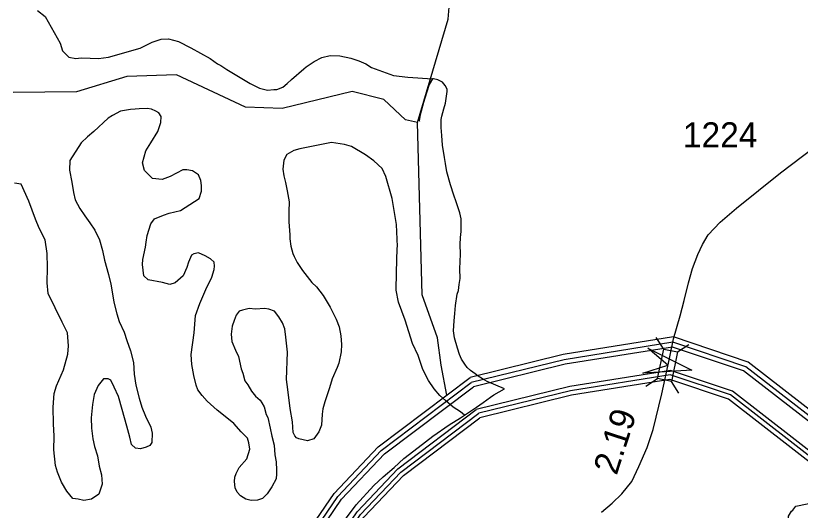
# Model space of a CAD drawing. Extents: x 2206922 to 2357709, y 510027 to 673830.
# Drawn here: x 2254245 to 2258161, y 585306 to 587773 of the extents above; entities that cross this region are included whole.
import ezdxf

# ---------------------------------------------------------------- set-up
doc = ezdxf.new("R2010")
doc.units = 0
for name, color, linetype in [('Exist Hydrographic Buffer Line', 7, 'Continuous'), ('Exist Hydrographic Creek Single Shore', 7, 'Continuous'), ('Exist Hydrographic Misc Water Feature', 7, 'Continuous'), ('Exist Hydrographic River Shore', 7, 'Continuous'), ('Exist Road Secondary Mileage Hundredths English Label', 7, 'Continuous'), ('Exist Road Secondary Structure Standard Bridge Attributed CELL', 7, 'Continuous'), ('Exist Road Secondary Structure Standard Bridge CELL', 7, 'Continuous'), ('Exist Road Secondary Type 51 Attributed', 7, 'Continuous'), ('Exist Road Secondary Type 51 Number Label', 7, 'Continuous')]:
    doc.layers.add(name, color=color, linetype=linetype)

msp = doc.modelspace()

# ---------------------------------------------------------------- linework, layer by layer
at = {"layer": 'Exist Hydrographic Buffer Line'}
for points in [[(2258439.8, 585595.2), (2257889, 586022.3), (2257525.7, 586143.9), (2256983.5, 586057.1), (2256519.2, 585943.3)], [(2258438.4, 585566.9), (2257877.9, 586001.6), (2257523.8, 586120.1), (2256988.1, 586034.4), (2256529.4, 585921.9)], [(2258495.1, 585470.3), (2258292.3, 585536.2), (2257823.5, 585899.8), (2257514.2, 586003.3), (2257010.6, 585922.7), (2256543.9, 585808.3)], [(2258496, 585447.9), (2258282.3, 585517.4), (2257813.4, 585881.1), (2257512.4, 585981.8), (2257014.8, 585902.2), (2256556.8, 585789.9)], [(2252449.5, 583777.6), (2252896.9, 583265.7), (2253032.5, 583222.4), (2253650, 583251.5), (2254012.5, 583205.2), (2254333.4, 583238.1), (2254389.7, 583270.4), (2254409.6, 583296.3), (2254490.2, 583536.5), (2254623, 583729.3), (2254736.7, 583794.1), (2255167, 584224.3), (2255561.4, 584946.9), (2255853.6, 585375.5), (2256070.1, 585604.4), (2256519.2, 585943.3)], [(2252443.6, 583749.1), (2252883.7, 583245.6), (2253029.4, 583199), (2253649.1, 583228.2), (2254012.2, 583181.9), (2254340.6, 583215.5), (2254405.3, 583252.6), (2254430.3, 583285.2), (2254511.1, 583526), (2254639.1, 583711.8), (2254750.9, 583775.5), (2255185.7, 584210.3), (2255581.2, 584934.8), (2255871.7, 585360.9), (2256085.6, 585587.1), (2256529.4, 585921.9)], [(2252451, 583555.4), (2252814.3, 583139.8), (2253013.2, 583076.2), (2253644.2, 583105.9), (2254010.7, 583059.2), (2254378.8, 583096.9), (2254487.1, 583159.1), (2254539.4, 583227.1), (2254621.3, 583471), (2254723.7, 583619.7), (2254825.5, 583677.7), (2255284.4, 584136.5), (2255685.3, 584871.1), (2255966.9, 585284.2), (2256167.2, 585495.9), (2256556.8, 585789.9)], [(2252461, 583578.1), (2252827.1, 583159.3), (2253016.2, 583098.9), (2253645.1, 583128.5), (2254011, 583081.9), (2254371.8, 583118.7), (2254472, 583176.3), (2254519.3, 583237.9), (2254601, 583481.1), (2254708.1, 583636.7), (2254811.7, 583695.7), (2255266.2, 584150.1), (2255666.1, 584882.8), (2255949.4, 585298.4), (2256152.1, 585512.7), (2256543.9, 585808.3)]]:
    msp.add_lwpolyline(points, dxfattribs=at)
at = {"layer": 'Exist Hydrographic Creek Single Shore'}
for points in [[(2256250.4, 587239.9), (2256404.4, 587754.9), (2256411.4, 587856.5)], [(2256250.4, 587239.9), (2256191.4, 587254.2), (2256082.5, 587354.8), (2255924.4, 587394), (2255575.4, 587309.3), (2255391.4, 587316.3), (2255048.4, 587477.4), (2254799.3, 587469.3), (2254549.3, 587392.4), (2254233.3, 587388.9)], [(2256397, 585880.8), (2256368.3, 586030.5), (2256350.5, 586165.4), (2256274.4, 586380.1), (2256250.4, 587239.9)], [(2258100.4, 585249.8), (2258101.8, 585264.2), (2258101.6, 585276), (2258117.4, 585302), (2258123.8, 585306.3), (2258139.3, 585326.2), (2258195.5, 585338.9), (2258359, 585366.1), (2258369.2, 585368.3), (2258375, 585370.2), (2258383, 585374.3), (2258391.2, 585380.4), (2258396.7, 585388.4)]]:
    msp.add_lwpolyline(points, dxfattribs=at)
at = {"layer": 'Exist Hydrographic Misc Water Feature'}
msp.add_line((2256631.6, 585881.6), (2256685.1, 585912.1), dxfattribs=at)
for points in [[(2254353.5, 587798.6), (2254391.8, 587768.8), (2254466.5, 587635.5), (2254479, 587597.6), (2254495.4, 587581.7), (2254511, 587565.9), (2254545.4, 587560), (2254571.2, 587562.1), (2254617.2, 587560.5), (2254659, 587559.1), (2254709, 587565.3), (2254866.5, 587610.5), (2254892.3, 587624.8), (2254926.4, 587641.2)], [(2254926.4, 587641.2), (2254972.1, 587655.4), (2255008.2, 587657.6), (2255057.8, 587644.1), (2255120.2, 587612.8), (2255215.1, 587559.6), (2255253, 587531.9), (2255269, 587523.8), (2255299.4, 587504.3), (2255357.6, 587468.7), (2255415.8, 587435.2), (2255461.6, 587411.7), (2255501.8, 587402), (2255534, 587404), (2255547.9, 587404.3), (2255578, 587416.4), (2255599.8, 587434.6), (2255621.5, 587454.9), (2255682.8, 587507.3), (2255694.7, 587517.3), (2255734.9, 587543.7), (2255772.6, 587563.9), (2255814.3, 587574.2), (2255862.5, 587572.6), (2255918.4, 587561.4), (2255958.6, 587547.6), (2255992.5, 587532), (2256021, 587513.9), (2256131.1, 587475), (2256202.8, 587465.4), (2256325, 587458.3)], [(2256325, 587458.3), (2256309.3, 587430.3), (2256297.4, 587392.3), (2256280.3, 587340.2), (2256264.4, 587278.1), (2256258.2, 587250.7), (2256260.9, 587246.2)], [(2256685.1, 585912.1), (2256599.2, 585947.8), (2256575.2, 585961.1), (2256552.9, 585975), (2256539.1, 585986.8), (2256514.9, 586002.7), (2256498.9, 586018.5), (2256486.6, 586034.5), (2256470.6, 586060.4), (2256460.2, 586082.3), (2256449.7, 586114.3), (2256435.4, 586166.3), (2256430.9, 586200.2), (2256432.9, 586250.2), (2256436.6, 586288.1), (2256440.3, 586328.2), (2256449.5, 586384), (2256455.7, 586402.1), (2256459.4, 586431.9), (2256463, 586462.2), (2256462.4, 586510.2), (2256465.9, 586584.2), (2256463.7, 586632), (2256465.1, 586665.9), (2256469.2, 586696.1), (2256468.4, 586760.3), (2256462.4, 586790), (2256444.2, 586843.8), (2256431.5, 586877.8), (2256415.5, 586929.7), (2256396.8, 586993.3), (2256390.7, 587035.2), (2256386.2, 587065.1), (2256375.7, 587127.1), (2256371.4, 587175.2), (2256369.1, 587214.9), (2256368.9, 587255), (2256372.4, 587271.1), (2256382.7, 587308.9), (2256390.3, 587337), (2256399.5, 587395.2), (2256399.3, 587407), (2256389.6, 587425.1), (2256375.3, 587441), (2256352.9, 587452.9), (2256331, 587458.6), (2256325, 587458.3)], [(2255420.4, 585354.1), (2255394.5, 585362.1), (2255366.6, 585377.7), (2255350.4, 585395.6), (2255340, 585417.8), (2255338.1, 585449.7), (2255339.6, 585471.4), (2255345.7, 585489.5), (2255361.3, 585519.6), (2255399, 585562.2), (2255414.6, 585610.1), (2255408.5, 585641.9), (2255402.1, 585665.9), (2255370.1, 585697.5), (2255333.6, 585739.5), (2255291.2, 585773.1), (2255251, 585804.7), (2255200.3, 585850.4), (2255176.6, 585877.9), (2255154.4, 585906), (2255146, 585929.6), (2255133.7, 585977.7), (2255125.1, 586033.7), (2255120.6, 586083.5), (2255136.2, 586191.5), (2255143.1, 586277.6), (2255164.7, 586337.6), (2255194.2, 586407.7), (2255223.7, 586468.2), (2255235.2, 586506.2), (2255237, 586524.2), (2255235.2, 586544.3), (2255216.9, 586560), (2255190.7, 586575.8), (2255156.9, 586589.4), (2255134.9, 586585.4), (2255122.8, 586579.1), (2255107, 586543), (2255099.2, 586517), (2255081.6, 586475), (2255042, 586440.4), (2255014.4, 586432.5), (2254978.1, 586442), (2254905.9, 586455.7), (2254884.1, 586475.2), (2254877.4, 586531.4), (2254879, 586557.1), (2254892.6, 586617.5), (2254896.2, 586643.2), (2254902, 586677.3), (2254919.8, 586735.4), (2254937.5, 586759.6), (2254983.4, 586778.2), (2255011.1, 586788.2), (2255067.1, 586800.8), (2255160.6, 586861.4), (2255172, 586897.4), (2255172, 586925.3), (2255170, 586951.6), (2255157.7, 586979.4), (2255127.3, 586999), (2255099.5, 587004.8), (2255079.4, 587004.6), (2255015.4, 586970.4), (2254976, 586955.7), (2254927.6, 586961.3), (2254887.4, 587001.1), (2254878.8, 587038.8), (2254894.4, 587099), (2254920.2, 587139.3), (2254953.9, 587195.5), (2254969.7, 587239.7), (2254971.3, 587269.5), (2254959, 587287.5), (2254944.8, 587297.4), (2254923.1, 587307.2), (2254901.4, 587309.2), (2254861.4, 587308.7), (2254841.1, 587306.5), (2254818.9, 587304.6), (2254769.1, 587295.9), (2254729.1, 587275.5), (2254707.6, 587261.4), (2254635.8, 587195.1), (2254604.3, 587168.6), (2254572.5, 587138.6), (2254515.3, 587049.9), (2254513.6, 587001.9), (2254526.1, 586942), (2254534.5, 586890.4), (2254542.9, 586854.3), (2254565.5, 586810.8), (2254589.7, 586774.7), (2254616.1, 586739.1), (2254640.3, 586703.4), (2254664.1, 586655.5), (2254678.9, 586601.4), (2254689.3, 586553.6), (2254708, 586481.9), (2254720.1, 586434.2)], [(2256484.8, 585780.5), (2256466.1, 585796.7), (2256428.4, 585820.2), (2256390.3, 585853.9), (2256362, 585877.7), (2256333.5, 585911.6), (2256305.2, 585953.1), (2256277.1, 586008.9), (2256254.3, 586078.8), (2256226, 586138.3), (2256189.1, 586254.1), (2256156.1, 586343.9), (2256143.4, 586403.7), (2256145.4, 586491.5), (2256149.9, 586613.6), (2256151.6, 586621.5), (2256145.4, 586731.5), (2256124.1, 586861.3), (2256092.9, 586971), (2256074.9, 587010.6), (2256032.6, 587048.2), (2255990.6, 587078.1), (2255922.1, 587119.6), (2255885.8, 587131.2), (2255822.1, 587140.4), (2255664.2, 587109.4), (2255634.2, 587101), (2255598.8, 587080.8), (2255583, 587052.7), (2255581.1, 587036.8), (2255579.1, 587006.7), (2255583.6, 586974.8), (2255591.6, 586940.7), (2255600.2, 586898.9), (2255610.4, 586845), (2255608.8, 586797), (2255609, 586745.1), (2255613.7, 586679.1), (2255613.9, 586659.2), (2255618, 586623.3), (2255628.7, 586587.2), (2255634.6, 586571.3), (2255650.8, 586541.7), (2255676.9, 586501.7), (2255699.6, 586471.9), (2255723.6, 586442.3), (2255745.8, 586420.3), (2255779.8, 586376.6), (2255814.9, 586319.1), (2255844.8, 586259.4), (2255859.4, 586221.5), (2255867.6, 586175.7), (2255871.9, 586133.6), (2255870.2, 586095.8), (2255858.8, 586039.5), (2255849.1, 586017.4), (2255825.3, 585961.4), (2255811.8, 585917.3), (2255788.4, 585846.9), (2255778.6, 585812.7), (2255774.9, 585784.9), (2255771.4, 585731.1), (2255757.7, 585697.1), (2255734.1, 585662.5), (2255702.1, 585652.3), (2255658.2, 585662.2), (2255646.1, 585668.1), (2255637.9, 585677.8), (2255629.9, 585693.6), (2255627.5, 585747.9), (2255615.2, 585813.5), (2255603.9, 585907.6), (2255597.3, 585957.7), (2255602.4, 586095.2), (2255593.8, 586169.1), (2255587.9, 586211.4), (2255577.4, 586241.3), (2255559, 586270.8), (2255536.8, 586298.9), (2255508.7, 586308.4), (2255486.8, 586312.1), (2255442.7, 586309.9), (2255411.1, 586311.8), (2255377.1, 586303.5), (2255361.1, 586299.5), (2255344.9, 586279.2), (2255335.5, 586253), (2255325.6, 586224.9), (2255319.9, 586185.2), (2255324.2, 586147.3), (2255342.6, 586105.1), (2255357, 586073.4), (2255371.4, 586011.6), (2255379.1, 585989.7), (2255388.2, 585951.5), (2255404, 585931.7), (2255422, 585900.1), (2255442.3, 585876), (2255464.6, 585854.4), (2255474.5, 585842.4)], [(2254500.7, 585400.7), (2254474.5, 585446.5), (2254453.7, 585496.2), (2254443.7, 585530.2), (2254435.1, 585608.1), (2254436.5, 585676.1), (2254434.1, 585738), (2254431.6, 585820), (2254436.9, 585888.1), (2254448.4, 585926.1), (2254483.9, 586006.3), (2254505, 586084.6), (2254508.9, 586126.6), (2254504.4, 586190.6), (2254477.9, 586244.1), (2254406.6, 586387.4), (2254402.1, 586439.6), (2254403.7, 586517.6), (2254402.9, 586587.5), (2254392.6, 586655.1), (2254362.3, 586712.9), (2254343.8, 586758.6), (2254310.8, 586848.3), (2254272.5, 586932), (2254238.6, 586937.9)], [(2254720.1, 586434.2), (2254732.8, 586356.1), (2254734.7, 586344), (2254749.4, 586286.2), (2254761.3, 586248.4), (2254785.9, 586194.7), (2254800.3, 586152.9), (2254818.7, 586101), (2254833.5, 586043.3), (2254836.2, 585985.2), (2254844.2, 585929.3), (2254860.8, 585865.5), (2254875.3, 585819.6), (2254893.4, 585775.9), (2254919.8, 585720), (2254926.4, 585690.2), (2254924.7, 585644.2), (2254914.7, 585629.9), (2254896.9, 585620), (2254868.8, 585611.7), (2254842.9, 585615.6), (2254822.6, 585633.3), (2254814.4, 585671.4), (2254800.1, 585725.1), (2254777.3, 585808.8), (2254758.7, 585872.8), (2254736.5, 585920.4), (2254720.1, 585954.5), (2254706, 585962.3), (2254683.8, 585962), (2254656.5, 585928), (2254636.9, 585883.5), (2254628.9, 585833.6), (2254621.9, 585767.8), (2254624.1, 585715.5), (2254630.5, 585661.8), (2254639.1, 585623.6), (2254653.1, 585577.7), (2254661.5, 585526.2), (2254673.8, 585482.1), (2254676.2, 585436.4), (2254660.6, 585386), (2254623.1, 585361.6), (2254585, 585355.6)], [(2256484.8, 585780.5), (2256545.9, 585821.1), (2256578.1, 585843.5), (2256615.6, 585869.8), (2256631.6, 585881.6)], [(2255474.5, 585842.4), (2255484.7, 585822.6), (2255495, 585784.5), (2255503, 585768.7), (2255515.7, 585714.9), (2255524.1, 585675.1), (2255534.6, 585631), (2255538.9, 585583.3), (2255544.8, 585547.1), (2255547.3, 585505.4), (2255547.1, 585487.1), (2255545.6, 585463.4), (2255524.1, 585423.3), (2255500.1, 585388.8), (2255476.5, 585364.7), (2255452.8, 585356.6), (2255420.4, 585354.1)], [(2255459.7, 584477.1), (2255496.8, 584565.2), (2255526.6, 584643.5), (2255555.5, 584725.9), (2255589.3, 584787.7), (2255610.4, 584834), (2255644.1, 584900.3), (2255669.7, 584962.5), (2255700.9, 585024.8), (2255754.6, 585096.9), (2255826.2, 585181.5), (2255880.9, 585248.2), (2255944.7, 585332.7), (2256033.5, 585429.2), (2256079.6, 585473.4), (2256135, 585520.2), (2256182.7, 585564.5), (2256254.3, 585619), (2256327.9, 585675.6), (2256409.1, 585732.3), (2256464.5, 585766.5), (2256484.8, 585780.5)], [(2254585, 585355.6), (2254557.1, 585361.4), (2254530.8, 585365), (2254500.7, 585400.7)]]:
    msp.add_lwpolyline(points, dxfattribs=at)
at = {"layer": 'Exist Hydrographic River Shore'}
for points in [[(2258435.6, 585631.1), (2257901.4, 586045.4), (2257527.9, 586170.4), (2256978.3, 586082.5), (2256513.1, 585968.4)], [(2252456.2, 583805.9), (2252910.5, 583286.3), (2253035.6, 583246.3), (2253651, 583275.3), (2254012.8, 583229.2), (2254325.9, 583261.2), (2254373.8, 583288.7), (2254388.3, 583307.6), (2254468.8, 583547.2), (2254606.6, 583747.3), (2254722.2, 583813.2), (2255147.8, 584238.7), (2255541.1, 584959.3), (2255835, 585390.5), (2256054.2, 585622.2), (2256513.1, 585968.4)], [(2258497.4, 585423.3), (2258271.4, 585496.8), (2257802.4, 585860.5), (2257510.5, 585958.2), (2257019.4, 585879.6), (2256562.3, 585767.6)], [(2252440.3, 583535.5), (2252802.3, 583121.5), (2253010.4, 583054.9), (2253643.4, 583084.8), (2254010.4, 583038), (2254385.5, 583076.3), (2254501.3, 583142.9), (2254558.3, 583217.1), (2254640.3, 583461.5), (2254738.4, 583603.8), (2254838.4, 583660.8), (2255301.4, 584123.7), (2255703.3, 584860.1), (2255983.4, 585270.9), (2256181.3, 585480.1), (2256562.3, 585767.6)]]:
    msp.add_lwpolyline(points, dxfattribs=at)
at = {"layer": 'Exist Road Secondary Structure Standard Bridge Attributed CELL'}
msp.add_lwpolyline([(2257401.1, 586114.3), (2257619.3, 586005.5), (2257375.9, 585990.6), (2257499.8, 586029.8)], close=True, dxfattribs=at)
at = {"layer": 'Exist Road Secondary Structure Standard Bridge CELL'}
for p, q in [((2257480.4, 586110.3), (2257442.7, 586168.1)), ((2257547.9, 586096), (2257605.7, 586133.6)), ((2257390.9, 585924.9), (2257448.7, 585962.5)), ((2257555.4, 585890), (2257517.8, 585947.9))]:
    msp.add_line(p, q, dxfattribs=at)
msp.add_lwpolyline([(2257448.7, 585962.5), (2257480, 586110.3), (2257549.1, 586095.7), (2257517.8, 585947.9)], close=True, dxfattribs=at)
at = {"layer": 'Exist Road Secondary Type 51 Attributed'}
for points in [[(2257507.7, 586062.8), (2257528.6, 586160.5), (2257561.3, 586276.1), (2257582, 586352), (2257602.7, 586440), (2257623.4, 586512.4), (2257649.3, 586581.4), (2257673.4, 586631.4), (2257701, 586679.7), (2257761.3, 586743.5), (2257842.4, 586812.5), (2258063, 586988.5), (2258226.8, 587114.4)], [(2257168.3, 585296.3), (2257221.7, 585341.2), (2257270, 585387.7), (2257320, 585449.8), (2257356.2, 585524), (2257397.6, 585618.9), (2257426.9, 585708.6), (2257470, 585886.3), (2257507.7, 586062.8)]]:
    msp.add_lwpolyline(points, dxfattribs=at)

# ---------------------------------------------------------------- texts
at = {"layer": 'Exist Road Secondary Mileage Hundredths English Label'}
msp.add_text('2.19', height=125, rotation=71.906, dxfattribs=at).set_placement((2257244.4, 585476.8))
at = {"layer": 'Exist Road Secondary Type 51 Number Label'}
msp.add_text('1224', height=125, dxfattribs=at).set_placement((2257575.4, 587116.1))

doc.saveas('drawing.dxf')
